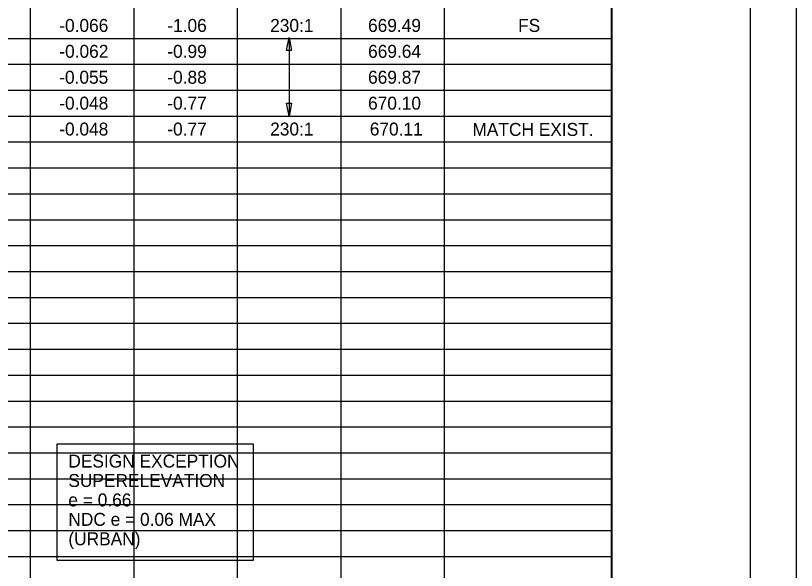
# Model space of a CAD drawing. Extents: x 0 to 34, y 0 to 22.
# Drawn here: x 25.55 to 34, y 4.83 to 10.83 of the extents above; entities that cross this region are included whole.
import ezdxf

# ---------------------------------------------------------------- set-up
doc = ezdxf.new("R2010")
doc.units = 0
for name, color, linetype in [('SH_Border', 7, 'Continuous'), ('SH_Cut_Line', 7, 'Continuous'), ('SH_Text', 7, 'Continuous')]:
    doc.layers.add(name, color=color, linetype=linetype)

msp = doc.modelspace()

# ---------------------------------------------------------------- linework, layer by layer
at = {"layer": 'SH_Border'}
msp.add_line((32, 0.5), (32, 21.5), dxfattribs=at)
msp.add_lwpolyline([(1.5, 21.5), (33.5, 21.5), (33.5, 0.5), (1.5, 0.5)], close=True, dxfattribs=at)
at = {"layer": 'SH_Cut_Line'}
msp.add_lwpolyline([(0, 0), (34, 0), (34, 22), (0, 22)], close=True, dxfattribs=at)
at = {"layer": 'SH_Text'}
for p, q in [((30.1918, 21.5), (30.1918, 0.5)), ((32.0036, 21.5), (32.0036, 0.5)), ((25.7118, 20.38), (25.7118, 0.5)), ((26.8318, 20.38), (26.8318, 0.5)), ((27.9518, 20.38), (27.9518, 0.5)), ((29.0718, 20.38), (29.0718, 0.5)), ((16.7518, 10.58), (32.0036, 10.58)), ((28.5118, 10.5882), (28.5118, 9.74)), ((16.7518, 10.3), (32.0036, 10.3)), ((16.7518, 10.02), (32.0036, 10.02)), ((16.7518, 9.74), (32.0036, 9.74)), ((16.7518, 9.46), (32.0036, 9.46)), ((16.7518, 9.18), (32.0036, 9.18)), ((16.7518, 8.9), (32.0036, 8.9)), ((16.7518, 8.62), (32.0036, 8.62)), ((16.7518, 8.34), (32.0036, 8.34)), ((16.7518, 8.06), (32.0036, 8.06)), ((16.7518, 7.78), (32.0036, 7.78)), ((16.7518, 7.5), (32.0036, 7.5)), ((16.7518, 7.22), (32.0036, 7.22)), ((16.7518, 6.94), (32.0036, 6.94)), ((16.7518, 6.66), (32.0036, 6.66)), ((16.7518, 6.38), (32.0036, 6.38)), ((16.7518, 6.1), (32.0036, 6.1)), ((16.7518, 5.82), (32.0036, 5.82)), ((16.7518, 5.54), (32.0036, 5.54)), ((16.7518, 5.26), (32.0036, 5.26)), ((16.7518, 4.98), (32.0036, 4.98))]:
    msp.add_line(p, q, dxfattribs=at)
for points in [[(28.4838, 10.4482), (28.5118, 10.5882), (28.5398, 10.4482)], [(28.5398, 9.88), (28.5118, 9.74), (28.4838, 9.88)], [(26.0055, 6.1973), (28.1255, 6.1973), (28.1255, 4.9375), (26.0055, 4.9375)]]:
    msp.add_lwpolyline(points, close=True, dxfattribs=at)

# ---------------------------------------------------------------- texts
for s, p in [('-0.066', (26.0263, 10.65)), ('-1.06', (27.1952, 10.65)), ('230:1', (28.3078, 10.65)), ('669.49', (29.3666, 10.65)), ('FS', (30.9898, 10.65)), ('-0.062', (26.027, 10.37)), ('-0.99', (27.1951, 10.37)), ('669.64', (29.367, 10.37)), ('-0.055', (26.0258, 10.09)), ('-0.88', (27.1951, 10.09)), ('669.87', (29.3667, 10.09)), ('-0.048', (26.0262, 9.81)), ('-0.77', (27.1952, 9.81)), ('670.10', (29.3669, 9.81)), ('-0.048', (26.0262, 9.53)), ('-0.77', (27.1952, 9.53)), ('230:1', (28.3078, 9.53)), ('670.11', (29.3854, 9.53)), ('MATCH EXIST.', (30.4956, 9.5259)), ('DESIGN EXCEPTION', (26.125, 5.9407)), ('SUPERELEVATION', (26.125, 5.7307)), ('e = 0.66', (26.125, 5.5207)), ('NDC e = 0.06 MAX', (26.125, 5.3107)), ('(URBAN)', (26.125, 5.1007))]:
    msp.add_text(s, height=0.14, dxfattribs=at).set_placement(p)

doc.saveas('drawing.dxf')
